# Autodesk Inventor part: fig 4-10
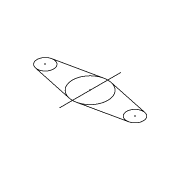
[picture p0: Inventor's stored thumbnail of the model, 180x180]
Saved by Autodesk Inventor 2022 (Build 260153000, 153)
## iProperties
Created: 2005-02
Part Number: fig 4-10
Document SubType Name: Modeling
Designer: CADCIM
Manufacturer: Standard
Standards Organization: Custom
Density: 1 g/cm^3
Material: Generic
Appearance: Default
Author: CADCIM
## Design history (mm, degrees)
sketch "Sketch1"
  geometry: L1 (-33.874, 5.844)-(-2.722, 12.469); L2 (-33.884, -5.902)-(-2.745, -12.585); L3 (-0.057, 22.288)-(-0.057, -22.318); L4 (33.759, 5.844)-(2.608, 12.469); L5 (33.77, -5.902)-(2.63, -12.585); A1 r 12.81 centre (-0.057, -0.06) between (-2.722, 12.469) and (-2.745, -12.585); A2 r 6.006 centre (-32.624, -0.03) between (-33.874, 5.844) and (-33.884, -5.902); A3 r 6.006 centre (32.51, -0.03) between (33.759, 5.844) and (33.77, -5.902)
  constraints: 10 end point, 6 point on circle, 5 symmetric about line, 4 tangent, 3 centre point, 1 vertical, 2 other
